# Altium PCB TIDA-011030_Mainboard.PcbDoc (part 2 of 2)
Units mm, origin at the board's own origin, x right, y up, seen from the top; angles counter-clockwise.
Board outline 65 x 19.54 mm, 4 copper layers (Top Layer, Inner Layer 1, Inner Layer 2, Bottom Layer), stack 1.586 mm thick; 113 components, 53 nets, 288 pads, 190 vias.
Unrouted connection lines stored in the file: 190.
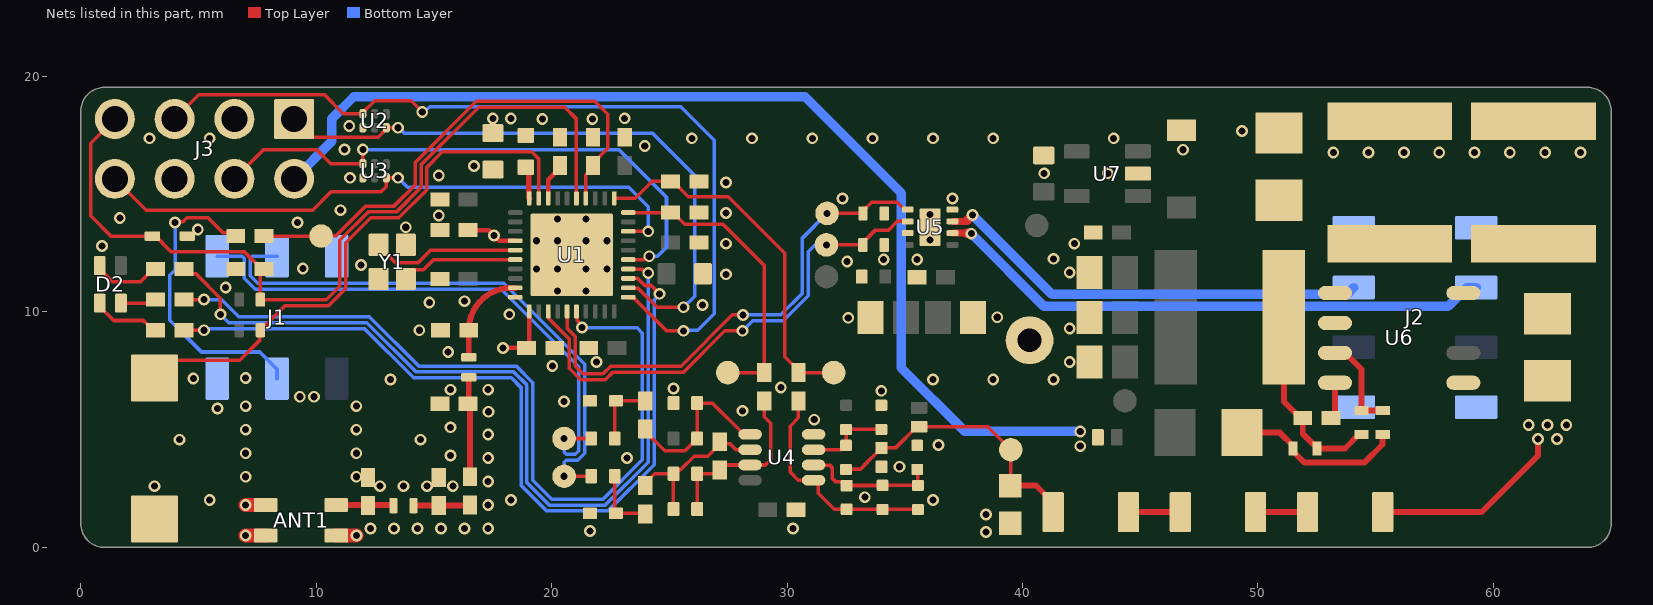
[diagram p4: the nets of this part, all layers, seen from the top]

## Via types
v1: diameter 0.5, hole 0.3, Top Layer to Bottom Layer, tented both sides, 186 vias
v2: diameter 0.443, hole 0.3, Top Layer to Bottom Layer, tented both sides, 4 vias

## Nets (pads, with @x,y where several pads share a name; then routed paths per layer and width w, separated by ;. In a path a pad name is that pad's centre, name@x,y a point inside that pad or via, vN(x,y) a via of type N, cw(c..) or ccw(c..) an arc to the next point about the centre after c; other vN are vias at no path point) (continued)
DRV_IN1/EN: R26.2 TP7.1 U1.3 U5.6 | length 21.3
  Top Layer w0.15: U1.3@19.85,10.025 19.875,10 19.875,9.725 20.747,8.853 20.747,7.603 21.225,7.125 22.281,7.125 22.604,7.448 25.604,7.448 27.356,9.2 v1(28.1,9.2) ; v1(31.67,12.85) R26.2@33.22,12.85 33.22,12.95 33.732,13.462 34.287,13.462 34.675,13.85 U5.6@35.12,13.85
  Bottom Layer w0.15: v1(28.1,9.2) 28.122,9.2 28.545,9.623 29.829,9.623 30.902,10.696 30.902,12.552 31.2,12.85 v1(31.67,12.85)
DRV_IN2/PWM: R25.2 TP8.1 U1.5 U5.5 | length 21.3
  Top Layer w0.15: U1.5@20.65,10.025 20.65,9.306 20.998,8.957 20.998,7.707 21.329,7.377 22.177,7.377 22.5,7.7 25.5,7.7 27.675,9.875 v1(28.125,9.875) ; v1(31.695,14.188) R25.2@33.223,14.188 33.223,14.288 33.6,14.665 34.68,14.665 34.995,14.35 U5.5@35.12,14.35
  Bottom Layer w0.15: v1(28.125,9.875) 29.725,9.875 30.65,10.8 30.65,13.143 v1(31.695,14.188)
DRV_OUT1: J2.4 U5.2 | length 23.9
  Top Layer w0.3: U5.2@37.02,13.35 v1@37.625,13.35
  Top Layer w0.4: v1@37.625,13.35 37.63,13.345 37.806,13.345 v1(37.825,13.326)
  Bottom Layer w0.4: v1(37.825,13.326) 40.913,10.238 58.068,10.238 58.87,11.04 J2.4@59.27,11.04
DRV_OUT2: J2.3 U5.3 | length 18.8
  Top Layer w0.3: U5.3@37.02,13.85 37.6,13.85 v1@37.7,13.95
  Top Layer w0.4: 37.65,13.9 v1(37.875,14.125)
  Bottom Layer w0.4: v1(37.875,14.125) 41.254,10.746 53.776,10.746 J2.3@54.07,11.04
GND: ANT1.2 ANT1.3 ANT1.4 C1.1 C2.2 C3.2 C5.2 C6.2 C7.2 C8.2 C9.2 C10.2 C11.2 C12.2 C13.2 C14.2 C16.1 C17.2 C18.2 C20.1 C21.2 C22.2 C23.2 C24.2 C25.2 C26.2 C29.2 C30.2 C31.2 C32.2 C33.2 C34.2 C35.2 D3.2 D7.2 D8.2 GND1.1 J1.1 J1.6 J2.1 J2.2 J3.3 J3.6 R9.1 R14.1 R17.1 R24.2 R25.1 R26.1 R27.1 SW1.1 U1.40 U1.41 U2.4 U3.4 U4.4 U5.4 U5.7 U5.9 U7.2 Y1.2 Y1.4 Z2.2 Z3.2 | length 2.6
  Top Layer w0.6: v1(7,0.5) ANT1.3@7.85,0.5 ; v1(7,1.8) ANT1.2@7.85,1.8 ; ANT1.4@10.85,0.5 11.7,0.5 ccw(c11.704,1.1) v1(11.702,0.5)
  other v1: 38.45,0.65 21.625,0.7 12.3,0.8 13.3,0.8 14.3,0.8 15.3,0.8 16.3,0.8 17.3,0.8 30.25,0.8 38.45,1.4 17.3,1.8 5.47,2.016 18.27,2.016 36.19,2.016 33.299,2.134 3.125,2.6 12.7,2.6 13.7,2.6 14.7,2.6 15.8,2.6 17.3,2.8 7,3 11.7,3 34.775,3.425 17.3,3.8 23.2,3.8 15.7,3.9 7,4 11.7,4 36.425,4.35 4.19,4.576 14.43,4.576 17.3,4.8 7,5 11.7,5 15.7,5.1 31.15,5.425 17.309,5.761 28.1,5.8 5.8,5.9 7,6 11.7,6 20.525,6.2 9.3,6.4 9.9,6.4 34,6.65 15.7,6.7 17.3,6.7 25.175,6.75 29.732,6.796 13.15,7.136 36.19,7.136 38.75,7.136 41.31,7.136 4.775,7.175 7,7.2 20.025,7.7 21.9,7.875 42,7.875 15.6,8.3 14.375,9.225 42,9.3 32.595,9.75 38.925,9.775 18.2,9.9 26.4,10.3 14.8,10.4 16.291,10.46 6.148,11.037 27.4,11.6 42,11.675 19.35,11.825 20.25,11.825 21.45,11.825 22.35,11.825 9.425,11.85 11.9,12 32.55,12.15 34.1,12.225 35.525,12.225 41.31,12.256 0.9,12.8 27.4,12.9 42.2,12.9 19.35,13.025 20.25,13.025 21.45,13.025 22.35,13.025 36.07,13.05 4.966,13.505 13.8,13.6 9.2,13.8 1.651,13.992 15.2,14.1 36.07,14.15 27.4,14.2 11.025,14.325 32.35,14.816 37.025,14.825 27.4,15.5 11.425,15.7 15.2,15.8 40.918,15.891 43.618,15.891 16.7,16.2 53.2,16.775 54.7,16.775 56.2,16.775 57.7,16.775 59.2,16.775 60.7,16.775 62.2,16.775 63.7,16.775 11.2,16.9 46.818,16.891 23.95,17.05 2.91,17.376 5.47,17.376 25.95,17.376 28.51,17.376 31.07,17.376 33.63,17.376 36.19,17.376 38.75,17.376 43.87,17.376 49.318,17.691 11.4,17.9 19.6,18.2 21.725,18.2 23.1,18.225
  other v2: 20.25,10.897 21.45,10.897 20.25,13.953 21.45,13.953
I_N: FB1.2 J1.4 TP4.1 | length 24.2
  Top Layer w0.15: v1(20.525,3.023) FB1.2@21.675,3.023
  Bottom Layer w0.15: J1.4@8.33,12.37 7.274,12.37 7.186,12.282 7.186,11.539 7.511,11.214 17.967,11.214 21.4,7.781 21.4,4 21.098,3.698 20.613,3.698 20.525,3.61 v1(20.525,3.023)
I_P: FB2.2 J1.2 TP6.1 | length 23.8
  Top Layer w0.15: v1(20.525,4.625) FB2.2@21.675,4.625
  Bottom Layer w0.15: J1.2@5.79,12.37 6.846,12.37 6.934,12.282 6.934,11.435 7.407,10.963 17.862,10.963 21.148,7.677 21.148,4.104 20.994,3.95 20.613,3.95 20.525,4.038 v1(20.525,4.625)
LED_B: R4.2 U1.14 | length 36.4
  Top Layer w0.15: R4.2@4.375,11.825 4.584,11.616 4.898,11.616 5.925,10.589 v1(5.925,9.9) ; U1.14@23.25,11.825 23.831,11.825 24.005,11.65 v1(24.1,11.65)
  Bottom Layer w0.15: v1(5.925,9.9) 6.277,9.548 12.146,9.548 14.243,7.452 18.393,7.452 18.948,6.896 18.948,2.746 19.896,1.798 22.279,1.798 24.1,3.619 v1(24.1,11.65)
LED_G: R3.2 U1.13 | length 35.6
  Top Layer w0.15: R3.2@4.375,9.225 v1(5.225,9.225) ; U1.13@23.25,11.425 23.654,11.425 23.954,11.125 24.222,11.125 24.479,10.868 24.479,10.676 v1(24.575,10.772)
  Bottom Layer w0.15: v1(5.225,9.225) 5.292,9.292 5.483,9.292 5.488,9.297 12.042,9.297 14.138,7.2 18.288,7.2 18.697,6.792 18.697,2.642 19.792,1.547 22.383,1.547 24.353,3.517 24.353,10.509 24.575,10.731 v1(24.575,10.772)
LED_R: R2.2 U1.6 | length 35
  Top Layer w0.15: R2.2@4.375,10.525 v1(5.225,10.525) ; U1.6@21.05,10.025 21.075,10 21.075,9.647 21.239,9.483 21.239,9.339 v1(21.288,9.339)
  Bottom Layer w0.15: v1(5.225,10.525) 5.978,10.525 6.703,9.8 12.25,9.8 14.347,7.703 18.497,7.703 19.2,7 19.2,2.85 20,2.05 22.175,2.05 23.848,3.723 23.848,9.102 23.625,9.325 21.302,9.325 v1(21.288,9.339)
Line: D6.2 J2.7 J2.8 R10.2 | length 8.3
  Top Layer w0.25: R10.2@55.3,1.5 59.5,1.5 61.9,3.9 v1(61.9,4.6)
  other v1: 62.7,4.6 61.5,5.2 62.3,5.2 63.1,5.2
MCU_ADC_I: C21.1 R21.2 TP5.1 U1.20 | length 12.8
  Top Layer w0.15: U1.20@23.25,14.225 25.046,14.225 C21.1@25.05,14.229 25.15,14.229 25.654,13.725 27.275,13.725 29.025,11.975 R21.2@29.025,7.425 TP5.1@27.475,7.425
MCU_ADC_V: C17.1 R13.2 TP3.1 U1.21 | length 15.6
  Top Layer w0.15: U1.21@22.65,14.825 23.55,14.825 24.275,15.55 C17.1@25.05,15.55 25.15,15.55 25.8,14.9 27.5,14.9 29.9,12.5 29.9,8.1 30.475,7.525 R13.2@30.475,7.425 TP3.1@31.975,7.425
MCU_RST: C13.1 D3.1 J3.7 R1.1 U1.25 | length 36.2
  Top Layer w0.15: J3.7@1.44,18.195 0.413,17.168 0.413,14.087 1.275,13.225 D3.1@3.035,13.225 3.17,13.225 3.845,12.55 6.95,12.55 7.675,11.825 C13.1@7.775,11.825 ; C13.1@7.725,11.775 7.625,11.675 R1.1@7.625,10.525 10.425,10.525 11,11.1 11,13.044 12.204,14.248 13.404,14.248 14.448,15.293 14.448,16.248 16.898,18.698 20.552,18.698 21.05,18.2 U1.25@21.05,14.825
MCU_SW: R5.1 SW1.2 U1.29 | length 24
  Top Layer w0.15: SW1.2@3.125,7.2 3.875,7.95 6.75,7.95 7.588,8.788 7.588,9.188 8.673,10.273 10.529,10.273 11.252,10.996 11.252,12.94 12.308,13.997 13.508,13.997 14.7,15.188 14.7,16.144 15.356,16.8 19.15,16.8 19.45,16.5 U1.29@19.45,14.825
MCU_SWDCK: J3.1 U1.12 U2.6 | length 26.8
  Top Layer w0.15: J3.1@9.06,18.195 9.83,17.425 12.625,17.425 U2.6@12.975,17.775 ; U2.6@12.975,17.825 v1(13.474,17.825) ; U1.12@23.25,11.025 23.275,11 23.675,11 24.475,10.2 v1(25.6,10.2)
  Bottom Layer w0.15: v1(13.474,17.825) 13.512,17.825 13.737,17.6 24.275,17.6 26.075,15.8 26.075,10.675 v1(25.6,10.2)
MCU_SWDIO: J3.5 U1.11 U2.3 | length 36.7
  Top Layer w0.15: J3.5@3.98,18.195 5.007,19.222 10.35,19.222 11.147,18.425 U2.3@11.975,18.425 11.975,18.475 12.475,18.975 14.025,18.975 v1(14.5,18.5) ; U1.11@23.25,10.625 23.275,10.6 23.475,10.6 24.875,9.2 v1(25.6,9.2)
  Bottom Layer w0.15: v1(14.5,18.5) 14.588,18.5 14.813,18.725 25.475,18.725 26.9,17.3 26.9,9.925 26.2,9.225 25.625,9.225 v1(25.6,9.2)
MCU_Temp: C14.1 R6.2 TP1.1 U1.24 | length 21.7
  Top Layer w0.15: R6.2@7.775,13.225 TP1.1@10.2,13.225 10.212,13.237 10.837,13.237 12.1,14.5 13.3,14.5 14.197,15.397 14.197,16.353 16.794,18.95 21.825,18.95 22.375,18.4 22.375,16.95 21.75,16.325 C14.1@21.75,16.225 21.75,16.125 21.45,15.825 U1.24@21.45,14.825
NetANT1_1: ANT1.1 Z1.1 Z2.1 | length 2.4
  Top Layer w0.248: ANT1.1@10.85,1.8 13.25,1.8 cw(c13.25,1.775) Z1.1@13.275,1.775
NetC1_2: C1.2 U1.28 | length 1.6
  Top Layer w0.2: U1.28@19.85,14.825 19.85,15.625 20.35,16.125 C1.2@20.35,16.225
NetC4_1: C4.1 C5.1 L1.1 | length 4.3
  Top Layer w0.248: C5.1@16.45,6.1 cw(c16.45,6.025) 16.525,6.025 C4.1@16.525,3 ; C5.1@16.475,6.075 L1.1@16.475,7.225
NetC4_2: C4.2 Z1.2 Z3.1 | length 2.4
  Top Layer w0.248: Z1.2@14.125,1.775 16.349,1.775 C4.2@16.525,1.8
NetC6_1: C6.1 L1.2 U1.39 | length 4.2
  Top Layer w0.248: L1.2@16.475,8.075 C6.1@16.475,9.225 cw(c18.275,9.225) 18.275,11.025 U1.39@18.45,11.025
NetC15_1: C15.1 R7.1 R8.1 R9.2 U4.2 | length 5.8
  Top Layer w0.15: U4.2@31.125,3.5 31.127,3.498 31.802,3.498 31.925,3.375 31.925,2.925 32.054,2.796 32.352,2.796 C15.1@32.527,2.621 32.535,2.629 34.045,2.629 R7.1@34.053,2.637 34.055,2.636 35.553,2.636 35.54,2.649 35.54,3.296 R9.2@35.525,3.311
NetC15_2: C15.2 R7.2 R8.2 R13.1 U4.1 | length 9.5
  Top Layer w0.15: R13.1@30.475,6.225 30.475,5.5 30.125,5.15 30.125,3.2 30.475,2.85 U4.1@31.125,2.85 31.186,2.85 31.325,2.711 31.325,2.3 32.004,1.621 C15.2@32.527,1.621 32.531,1.617 34.049,1.617 R7.2@34.053,1.612 34.055,1.611 35.553,1.611 R8.2@35.555,1.609
NetC16_2: C16.2 D4.2 R12.1 R14.2 R15.1 TP2.1 | length 12.2
  Top Layer w0.15: R15.1@32.502,3.311 33.099,3.311 33.394,3.605 33.394,3.617 33.867,4.09 33.878,4.09 C16.2@34.013,4.225 34.605,4.225 35.505,5.125 D4.2@35.605,5.125 38.525,5.125 TP2.1@39.5,4.15 R14.2@39.5,2.65
  Top Layer w0.25: R14.2@39.5,2.65 R14.2@39.475,2.625 40.575,2.625 41.3,1.9 R12.1@41.3,1.5
NetC19_1: C19.1 R18.1 R19.1 R21.1 U4.7 | length 7.5
  Top Layer w0.15: R18.1@26.187,1.625 26.187,3.127 26.975,3.127 C19.1@27.138,3.29 27.348,3.5 U4.7@28.425,3.5 29.075,3.5 29.3,3.725 29.3,5.275 29.025,5.55 R21.1@29.025,6.225
NetC19_2: C19.2 R18.2 R19.2 R20.2 U4.6 | length 7
  Top Layer w0.15: R20.2@23.975,2.625 23.975,2.725 24.377,3.127 R19.2@25.162,3.127 ; R18.2@25.162,1.625 R19.2@25.162,3.127 ; U4.6@28.425,4.15 28.419,4.156 27.819,4.156 27.575,4.4 27.229,4.4 27.188,4.44 C19.2@27.138,4.49 27.138,4.39 26.624,3.876 26.048,3.876 25.469,3.296 25.325,3.296 25.162,3.134 R19.2@25.162,3.127
NetC20_2: C20.2 FB1.1 R20.1 | length 2.9
  Top Layer w0.15: FB1.1@22.675,3.023 22.675,1.496 C20.2@22.725,1.446 23.954,1.446 R20.1@23.975,1.425
NetC22_1: C22.1 FB2.1 R23.1 | length 2.9
  Top Layer w0.15: FB2.1@22.675,4.625 22.675,6.175 C22.1@22.725,6.225 R23.1@23.975,6.225
NetC27_1: C27.1 D5.1 R28.2 | length 7.4
  Top Layer w0.25: D5.1@49.325,4.875 50.931,4.875 51.492,4.314 C27.1@51.492,4.2 51.492,4.086 51.978,3.6 54.519,3.6 55.292,4.373 55.292,4.784 R28.2@55.3,4.792
NetC27_2: C27.2 C28.2 D8.1 L3.1 R29.1 U6.1 U6.2 | length 8.4
  Top Layer w0.25: L3.1@51.1,9.775 51.1,6.2 51.8,5.5 C28.2@51.9,5.5 51.9,4.825 52.345,4.38 52.443,4.38 52.508,4.314 C27.2@52.508,4.2 53.694,4.2 54.286,4.792 R29.1@54.4,4.792
NetC28_1: C28.1 U6.4 | length 1.6
  Top Layer w0.25: C28.1@53.1,5.5 53.275,5.675 U6.4@53.275,6.995
NetC29_1: C29.1 C30.1 D6.1 U6.5 U6.8
NetD1_2: D1.2 J3.2 | length 45.6
  Bottom Layer w0.4: J3.2@9.06,15.655 10.65,17.245 10.65,18.2 11.59,19.14 30.76,19.14 34.85,15.05 34.85,7.625 37.55,4.925 v1(42.45,4.925)
  other v1: 42.45,4.3
NetD2_1: D2.1 R2.1 | length 1.5
  Top Layer w0.15: D2.1@1.7,10.375 3.025,10.375 R2.1@3.175,10.525
NetD2_2: D2.2 R3.1 | length 2.9
  Top Layer w0.15: D2.2@0.8,10.375 0.8,10.225 1.387,9.637 2.645,9.637 2.833,9.45 2.95,9.45 R3.1@3.175,9.225
NetD2_3: D2.3 R4.1 | length 3
  Top Layer w0.15: D2.3@0.8,11.975 0.8,11.825 1.35,11.275 2.525,11.275 3.075,11.825 R4.1@3.175,11.825
NetJ1_3: J1.3 R6.1 | length 13
  Top Layer w0.15: v1(4,13.8) 4.036,13.836 4.336,13.836 4.5,14 5.4,14 6.038,13.362 6.438,13.362 R6.1@6.575,13.225
  Bottom Layer w0.15: v1(4,13.8) 4,11.79 3.775,11.565 3.775,9.65 5.125,8.3 7.6,8.3 7.905,7.995 8.33,7.57 J1.3@8.33,7.17
NetL2_1: L2.1 U1.30 | length 1.4
  Top Layer w0.25: L2.1@18.9,16.15 19.025,16.025 19.025,14.85 U1.30@19.05,14.825
NetR10_1: R10.1 R11.2 | length 2.2
  Top Layer w0.25: R11.2@49.9,1.5 R10.1@52.1,1.5
NetR11_1: R11.1 R12.2 | length 2.2
  Top Layer w0.25: R12.2@44.5,1.5 R11.1@46.7,1.5
NetR15_2: R15.2 R16.1 R17.2 U4.3 | length 3.6
  Top Layer w0.15: U4.3@31.125,4.15 32.303,4.15 32.489,4.336 R15.2@32.502,4.336 R16.1@32.502,5.013 R17.2@34.003,5.012
NetR22_2: R22.2 R23.2 R24.1 U4.5 | length 7.2
  Top Layer w0.15: R23.2@23.975,5.025 23.975,4.925 24.8,4.1 25.659,4.1 26.012,4.454 26.025,4.454 26.187,4.616 26.187,4.629 26.187,6.131 26.819,6.131 28.15,4.8 U4.5@28.425,4.8
NetR28_1: R28.1 R29.2 U6.3 | length 4.1
  Top Layer w0.25: U6.3@53.275,8.265 53.7,8.265 54.4,7.565 R29.2@54.4,5.808 R28.1@55.3,5.808
NetU1_35: U1.35 Y1.3 | length 6.4
  Top Layer w0.15: Y1.3@12.65,12.85 12.65,12.8 13.35,12.1 14.325,12.1 14.85,12.625 U1.35@18.45,12.625
NetU1_36: U1.36 Y1.1 | length 5
  Top Layer w0.15: Y1.1@13.8,11.4 13.8,11.45 14.15,11.8 14.55,11.8 14.975,12.225 U1.36@18.45,12.225
UART_RX: J3.8 U1.18 U3.6 | length 26.4
  Top Layer w0.15: J3.8@1.44,15.655 2.77,14.325 9.85,14.325 10.625,15.1 12.75,15.1 12.975,15.325 U3.6@12.975,15.7 v1(13.475,15.7) ; U1.18@23.25,13.425 v1(24.1,13.425)
  Bottom Layer w0.15: v1(13.475,15.7) 13.875,15.3 23.275,15.3 24.1,14.475 v1(24.1,13.425)
UART_TX: J3.4 U1.15 U3.3 | length 24.5
  Top Layer w0.15: J3.4@6.52,15.655 7.765,16.9 10.007,16.9 10.607,16.3 U3.3@11.975,16.3 v1(11.975,16.9) ; U1.15@23.25,12.225 23.905,12.225 24.047,12.367 v1(24.142,12.367)
  Bottom Layer w0.15: v1(11.975,16.9) 22.85,16.9 24.875,14.875 24.875,12.75 24.492,12.367 v1(24.142,12.367)
VDDR: C2.1 C3.1 C12.1 L2.2 U1.1 U1.34 | length 4.8
  Top Layer w0.2: C3.1@16.45,13.475 17.325,13.475 v1(17.55,13.25) 17.775,13.025 U1.34@18.45,13.025 ; v1(17.925,8.475) C2.1@18.925,8.475 19.05,8.6 U1.1@19.05,10.025
  other v1: 17.499,18.223 18.263,18.22
pads on no net: J2.5 J2.6 U1.2 U1.4 U1.7 U1.9 U1.10 U1.16 U1.19 U1.22 U1.26 U1.27 U1.32 U1.33 U1.37 U2.2 U2.5 U3.2 U3.5 U6.6 U7.3 U7.4

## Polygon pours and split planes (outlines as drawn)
GND on Top Layer "Top Layer-GND" (solid, remove dead copper, pour order 36): 43.8,15.489 43.5,15.205 43.5,0 11.35,0 11.35,6 7.35,6 7.35,0 0,0 0,19.5 65,19.5 65,16.4 47.7,16.4 47.4,16.1 47.4,15.7 47.189,15.489
5V on Top Layer "TOP_LAYER_5V_P000" (solid, remove dead copper, pour order 0): 37.5,13 36.75,13 36.75,12.625 36.325,12.2 36.325,11.2 35.6,10.475 34.5,10.475 34.5,9.075 36.95,9.075 36.95,10.475 37.5,11.025
VDDR on Top Layer "TOP_LAYER_VDDR_P001" (solid, remove dead copper, pour order 1): 19.25,17 15.3,17 15.3,18.575 19.25,18.575
NetD1_2 on Top Layer "TOP_LAYER_NETD1_2_P030" (solid, remove dead copper, pour order 30): 42.15,5.25 42.15,4 43.45,4 43.45,5.25
5V on Top Layer "Top Layer-5V" (solid, remove dead copper, pour order 28): 43.7,4.375 44.2,3.875 47.4,3.875 47.4,15.175 47.2,15.375 43.9,15.375 43.7,15.175 43.7,6.275 43.7,5.175
NetC29_1 on Top Layer "TOP_LAYER_NETC29_1_P005" (solid, remove dead copper, pour order 5): 60,6.6 59.6,6.2 57.6,6.2 57.2,6.6 57.2,9.6 54.7,12.1 52.95,12.1 52.95,13.7 64.9,13.7 64.9,9 60.4,9 60,8.6
NetC27_2 on Top Layer "TOP_LAYER_NETC27_2_P010" (solid, remove dead copper, pour order 10): 54.1,11.275 54.1,9.175 52.4,9.175 52.2,8.975 52.2,6.875 50.2,6.875 50.2,12.6 49.8,13 49.8,15.675 51.925,15.675 52,15.6 52,11.775 52.5,11.275
Line on Top Layer "TOP_LAYER_LINE_P023" (solid, remove dead copper, pour order 23): 61.2,8 63.4,8 63.4,4.3 61.2,4.3
3.3V on Top Layer "TOP_LAYER_3.3V_P024" (solid, remove dead copper, pour order 24): 43,15.575 40.3,15.575 40.3,13.375 43,13.375
Line on Bottom Layer "BOTTOM_LAYER_LINE_P037" (solid, remove dead copper, pour order 37): 53.1,6.5 53.1,4.1 63.9,4.1 63.9,6.5
GND on Bottom Layer "Bottom Layer-GND" (solid, remove dead copper, pour order 34): 0,0 7.35,0 7.35,6 11.35,6 11.35,0 50.8,0 50.8,9.1 65,9.1 65,19.5 0,19.5
NetD1_2 on Bottom Layer "BOTTOM_LAYER_NETD1_2_P025" (solid, remove dead copper, pour order 25): 42.15,5.25 42.15,4 42.75,4 42.75,5.25
GND on Inner Layer 1 "Inner Layer 1-GND" (solid, remove dead copper, pour order 33): 0,0 7.35,0 7.35,6 11.35,6 11.35,0 65,0 65,2.6 59.5,2.6 59.5,7.2 63.1,7.2 65,7.2 65,19.5 0,19.5
VDDR on Inner Layer 2 "INNER_LAYER_2_VDDR_P029" (solid, remove dead copper, pour order 29): 17.2,18.4 17.2,16 17.2,14.4 17.2,8.4 17.4,8.2 18.3,8.2 18.5,8.4 18.5,18.4 18.4,18.5 17.3,18.5
3.3V on Inner Layer 2 "Inner Layer 2-3.3V" (solid, remove dead copper, pour order 32): 0,0 7.35,0 7.35,6 11.35,6 11.35,0 45.4,0 45.4,19.5 0,19.5

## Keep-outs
Keep-Out Layer:
  text ".Layer_Name" at 14.656,-21.806 h1.52

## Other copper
Top Layer:
  text ".Layer_Name" at 14.656,-21.806 h1.52
Bottom Layer:
  text ".Layer_Name" at 14.656,-21.806 h1.52

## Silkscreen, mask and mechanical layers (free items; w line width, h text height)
Top Overlay:
  circle w0.254: c31.468,2.121 r0.141
  circle w0.254: c11,18.2 r0.141
  lines w0.2: 12.95,16.8 13.45,16.8 13.45,16.4 ; 12.95,18.9 13.45,18.9 13.45,18.5
  text "TLV709A33" at 38.45,17.825 h0.76
  text ".PRJ_Number" at 25.41,17.052 h1.1
  text "DRV8213" at 32.142,15.05 h0.76
  text "CC234x" at 22.847,9 h0.76
  text "UCC28881" at 53.7,3.2 h0.76
  text "OPA2323" at 31.2,0.225 h0.76
  text ".Layer_Name" at 14.656,-21.806 h1.52
Bottom Overlay:
  lines w0.2: 12,16.9 26.7,16.9 ; 15,15.5 15,18.3 ; 19.3,15.5 19.3,18.3 ; 22.2,15.5 22.2,18.3 ; 12,15.5 12,18.3 26.7,18.3 26.7,15.5 12,15.5
  text "RST" at 14.516,17.219 h0.76
  text "SWDIO" at 18.914,17.219 h0.76
  text "GND" at 21.816,17.219 h0.76
  text "SWDCK" at 26.177,17.219 h0.76
  text "RX" at 14.235,15.819 h0.76
  text "GND" at 18.216,15.819 h0.76
  text "TX" at 21.435,15.819 h0.76
  text "5V" at 25.035,15.819 h0.76
  text "DANGER HIGH VOLTAGE" at 64,1.1 h1.52
  text ".Layer_Name" at 14.656,-21.806 h1.52
Top Paste:
  text ".Layer_Name" at 14.656,-21.806 h1.52
Bottom Paste:
  text ".Layer_Name" at 14.656,-21.806 h1.52
Top Solder:
  text ".Layer_Name" at 14.656,-21.806 h1.52
  text ".Layer_Name" at 14.656,-21.806 h1.52
Bottom Solder:
  text ".Layer_Name" at 14.656,-21.806 h1.52
Drill Guide:
  text ".Layer_Name" at 14.656,-21.806 h1.52
M1 Board Outline:
  the board outline again, w0.254
  text ".Layer_Name" at 14.656,-21.806 h1.52
M2 Board Dimensions:
  rectangle: 3.175,-10.16 12.7,-6.985
  rectangle: 0,-6.985 3.175,-3.81
  lines w0.178: 0,-6.985 25.4,-6.985 ; 3.175,-10.16 3.175,-3.81 ; 6.35,-10.16 6.35,-3.81 ; 12.7,-10.16 12.7,-3.81 ; 19.05,-10.16 19.05,-3.81 ; 0,-10.16 0,-3.81 25.4,-3.81 25.4,-10.16 0,-10.16
  text ".Layer_Name" at 14.656,-21.806 h1.52
M3 3D STEP Top:
  text ".Layer_Name" at 14.656,-21.806 h1.52
M4 3D STEP Bottom:
  text ".Layer_Name" at 14.656,-21.806 h1.52
M5 Assembly Top:
  lines w0.254: -7.417,-23.626 160.223,-23.626 ; -7.417,-18.462 160.274,-18.462 ; -7.417,-13.297 -7.417,-28.791 94.31,-28.791 160.274,-28.791 160.274,-13.297 -7.404,-13.297 -7.404,-28.791 32.614,-28.791 ; 55.194,-28.791 55.194,-13.297 ; 87.376,-18.462 87.376,-13.297 ; 108.712,-18.462 108.712,-13.297 ; 124.511,-28.956 124.511,-23.804
  text "COMPONENTS MARKED 'DNP' SHOULD NOT BE POPULATED." at 29.299,-8.09 h1.52
  text "ASSEMBLY VARIANT:" at 29.286,-11.024 h1.52
  text ".VariantName" at 55.601,-11.024 h1.52
  text "PCB VIEWED FROM TOP SIDE" at -5.804,-16.654 h1.52
  text "BOARD #:" at 57.099,-16.654 h1.52
  text ".PRJ_Number" at 70.955,-16.654 h1.52
  text "REV:" at 92.405,-16.654 h1.52
  text ".PCB_Rev" at 99.809,-16.654 h1.52
  text "SVN REV:" at 113.69,-16.654 h1.52
  text ".VersionControl_RevNumber" at 126.543,-16.654 h1.52
  text "PLOT NAME =" at -5.804,-27.034 h1.52
  text ".plot_File_Name" at 14.656,-27.034 h1.52
  text "GENERATED    :" at 57.15,-27.034 h1.52
  text ".Print_Date" at 79.235,-27.034 h1.52
  text ".Print_Time" at 97.752,-27.034 h1.52
  text "TEXAS INSTRUMENTS" at 129.87,-27.034 h1.52
M6 Assembly Bottom:
  lines w0.254: -7.429,-18.474 160.261,-18.474 ; -7.379,-23.639 160.261,-23.639 ; 28.334,-28.969 28.334,-23.817 ; 44.133,-18.474 44.133,-13.31 ; 65.468,-18.474 65.468,-13.31 ; 97.65,-28.804 97.65,-13.31 ; 120.231,-28.804 160.249,-28.804 160.249,-13.31 -7.429,-13.31 -7.429,-28.804 58.534,-28.804 160.261,-28.804 160.261,-13.31
  text "COMPONENTS MARKED 'DNP' SHOULD NOT BE POPULATED." at 154.991,-8.077 h1.52
  text ".VariantName" at 128.473,-11.024 h1.52
  text "ASSEMBLY VARIANT:" at 154.864,-11.024 h1.52
  text ".VersionControl_RevNumber" at 26.302,-16.667 h1.52
  text "SVN REV:" at 39.154,-16.667 h1.52
  text ".PCB_Rev" at 53.035,-16.667 h1.52
  text "REV:" at 60.439,-16.667 h1.52
  text ".PRJ_Number" at 81.89,-16.667 h1.52
  text "BOARD #:" at 95.745,-16.667 h1.52
  text "PCB VIEWED FROM BOTTOM SIDE" at 158.648,-16.667 h1.52
  text "TEXAS INSTRUMENTS" at 22.974,-27.047 h1.52
  text ".Print_Time" at 55.093,-27.047 h1.52
  text ".Print_Date" at 73.609,-27.047 h1.52
  text "GENERATED    :" at 95.694,-27.047 h1.52
  text ".plot_File_Name" at 138.189,-27.047 h1.52
  text "PLOT NAME =" at 158.648,-27.047 h1.52
M9 Title Sheet:
  drawing of 63 lines, arcs and shapes, not listed
  text "1" at 35.293,466.75 h1.78
  text "2" at 136.766,466.75 h1.78
  text "3" at 238.239,466.75 h1.78
  text "4" at 339.865,466.75 h1.78
  text "5" at 441.423,466.75 h1.78
  text "6" at 542.98,466.75 h1.78
  text "7" at 644.623,466.75 h1.78
  text "8" at 746.096,466.75 h1.78
  text "A" at -11.874,405.841 h1.78
  text "A" at 793.305,405.841 h1.78
  text "B" at -11.874,278.841 h1.78
  text "B" at 793.305,278.841 h1.78
  text "C" at -11.874,151.841 h1.78
  text "C" at 793.305,151.841 h1.78
  text "D" at -11.874,24.841 h1.78
  text "D" at 793.305,24.841 h1.78
  text "PROJECT TITLE:" at 714.947,6.823 h1.14
  text ".PRJ_Title" at 716.216,3.436 h1.78
  text "DESIGNED FOR:" at 714.947,-0.823 h1.14
  text ".PRJ_Customer" at 716.216,-4.379 h1.78
  text "FILE NAME:" at 714.947,-8.443 h1.14
  text ".PCB_File_Name_No_Path" at 716.216,-11.491 h1.78
  text "Texas Instruments (TI) and/or its licensors do not warrant the accuracy or completeness of this specification" at 588.721,-15.601 h1.14
  text "ENGINEER:" at 714.947,-15.809 h1.14
  text "LAYOUT BY:" at 753.173,-15.809 h1.14
  text "or any information contained therein. TI and/or its licensors do not warrant that this design will meet" at 587.579,-18.463 h1.14
  text ".PRJ_Engineer" at 716.216,-19.746 h1.78
  text ".PCB_Layout" at 754.456,-19.746 h1.78
  text "the specifications, will be suitable for your application or fit for any particular purpose, or will operate in" at 587.579,-21.325 h1.14
  text ".Layer_Name" at 14.656,-21.806 h1.52
  text "ALTIUM DESIGNER VERSION:" at 753.173,-23.683 h1.14
  text "an implementation. TI and/or its licensors do not warrant that the design is production worthy. You should" at 587.579,-24.187 h1.14
  text "completely validate and test your design implementation to confirm the system functionality for your application." at 588.721,-27.048 h1.14
  text ".print_Scale" at 716.216,-27.069 h1.78
  text ".Application_BuildNumber" at 754.456,-27.069 h1.78
  text "1" at 35.293,-33.503 h1.78
  text "2" at 136.766,-33.503 h1.78
  text "3" at 238.239,-33.503 h1.78
  text "4" at 339.865,-33.503 h1.78
  text "5" at 441.423,-33.503 h1.78
  text "6" at 542.98,-33.503 h1.78
  text "7" at 644.623,-33.503 h1.78
  text "8" at 746.096,-33.503 h1.78
M10 Fab Notes:
  drawing of 189 lines, arcs and shapes, not listed
  text "DESIGN INFORMATION" at 741.376,161.675 h1.52
  text "MIN. TRACK WIDTH:" at 725.004,158.319 h1.52
  text "8" at 752.848,158.32 h1.52
  text "MIL" at 756.779,158.319 h1.52
  text "MIN. CLEARANCE:" at 725.004,155.167 h1.52
  text "7.874" at 748.5,155.167 h1.52
  text "MIL" at 756.779,155.167 h1.52
  text "MIN. VIA PAD SIZE:" at 725.004,152.014 h1.52
  text "24" at 752.087,152.014 h1.52
  text "MIL" at 756.779,152.014 h1.52
  text "0.05mm (2MIL)" at 742.657,148.714 h1.52
  text "MINIMUM ANNULAR RING" at 716.641,148.506 h1.52
  text "EXTERNAL" at 760.64,148.506 h1.52
  text "PER" at 721.721,145.708 h1.52
  text "IPC-D-275 CLASS 2 LEVEL C" at 727.309,145.708 h1.52
  text "MIL, HOLES" at 765.11,143.156 h1.52
  text "+/-" at 755.142,142.938 h1.52
  text "+/-" at 776.834,142.938 h1.52
  text "REGISTRATION TOLERANCES:" at 716.641,142.911 h1.52
  text "METAL" at 747.116,142.911 h1.52
  text "5" at 761.751,142.911 h1.52
  text "3" at 782.909,142.911 h1.52
  text "MIL" at 785.862,142.911 h1.52
  text "HOLE SIZE TOLERANCE (UNLESS OTHERWISE SPECIFIED):" at 716.641,140.414 h1.52
  text "+/-" at 776.834,140.341 h1.52
  text "3" at 782.909,140.314 h1.52
  text "MIL" at 785.862,140.314 h1.52
  text "MATERIAL:" at 714.742,136.818 h1.52
  text "FR-4 High Tg" at 739.798,133.553 h1.52
  text "X" at 736.129,133.35 h1.52
  text "FR-4" at 725.436,133.235 h1.52
  text "OTHER" at 763.231,133.235 h1.52
  text "62 MIL (1.6mm) +/-10%" at 733.566,129.602 h1.52
  text "X" at 730.516,129.54 h1.52
  text "THICKNESS:" at 716.641,129.394 h1.52
  text "OTHER" at 766.203,129.394 h1.52
  text "TOLERANCE:" at 716.641,125.88 h1.52
  text "X" at 738.187,125.88 h1.52
  text "ANSI IPC-6012 TYPE 3 CLASS 2" at 742.708,125.88 h1.52
  text "OTHER +/-" at 742.708,122.218 h1.52
  text "BOW & TWIST:" at 716.641,118.53 h1.52
  text "X" at 738.187,118.53 h1.52
  text "ANSI IPC-6012 TYPE 3 CLASS 2" at 742.708,118.53 h1.52
  text "OTHER +/-" at 742.708,114.804 h1.52
  text "DRILLING:" at 714.742,111.486 h1.52
  text "NC_DRILL FILES" at 759.472,108.815 h1.52
  text "REFERENCE:" at 716.641,108.715 h1.52
  text "X" at 733.335,108.712 h1.52
  text "AS SHOWN" at 737.856,108.715 h1.52
  text "X" at 756.221,108.715 h1.52
  text "OTHER" at 767.041,105.101 h1.52
  text "PTH COPPER THICKNESS:" at 716.633,105.012 h1.52
  text "X" at 745.57,105.012 h1.52
  text "20-30 um" at 748.821,105.012 h1.52
  text "BOARD FINISH:" at 714.742,101.263 h1.52
  text "SILKSCREEN:" at 718.685,98.466 h1.52
  text "X" at 743.013,98.466 h1.52
  text "TOP" at 745.984,98.466 h1.52
  text "X" at 755.967,98.466 h1.52
  text "BOTTOM" at 758.964,98.466 h1.52
  text "SILKSCREEN COLOR:" at 718.685,94.524 h1.52
  text "X" at 742.987,94.524 h1.52
  text "WHITE" at 745.984,94.524 h1.52
  text "OTHER" at 758.964,94.524 h1.52
  text "X" at 746.315,90.88 h1.52
  text "GREEN" at 749.312,90.88 h1.52
  text "OTHER" at 765.009,90.88 h1.52
  text "SOLDER RESIST COLOR:" at 718.685,90.706 h1.52
  text "X" at 746.315,86.962 h1.52
  text "MATTE" at 749.312,86.962 h1.52
  text "SEMI-GLOSS" at 764.997,86.946 h1.52
  text "IMMERSION GOLD (ENIG)" at 741.692,82.574 h1.52
  text "ENEPIG" at 775.665,82.39 h1.52
  text "SURFACE FINISH:" at 714.742,82.365 h1.52
  text "X" at 737.171,82.365 h1.52
  text "IMM. TIN/SILVER OR EQUIV" at 723.113,78.877 h1.52
  text "OTHER" at 759.472,78.777 h1.52
  text "ARRAY/PANEL:" at 714.742,74.831 h1.52
  text "CUT AND TRIM PER M1 BOARD OUTLINE" at 741.692,74.622 h1.52
  text "N.C. ROUTE" at 741.692,71.168 h1.52
  text "X" at 759.167,71.168 h1.52
  text "V. SCORE" at 763.688,71.168 h1.52
  text "CERTIFICATION:" at 714.742,67.888 h1.52
  text "MATERIALS AND WORKMANSHIP FOR ALL PCBS" at 733.157,67.888 h1.52
  text "TO MEET OR EXCEED THE REQUIREMENTS OF:" at 733.157,65.499 h1.52
  text "X" at 723.95,62.232 h1.52
  text "ANSI IPC-A-600F CLASS ->" at 727.201,62.232 h1.52
  text "X" at 769.06,62.232 h1.52
  text "2" at 771.854,62.232 h1.52
  text "1" at 763.853,62.194 h1.52
  text "3" at 780.846,62.194 h1.52
  text "X" at 744.575,58.481 h1.52
  text "RoHS" at 747.826,58.481 h1.52
  text "OTHER" at 764.194,58.481 h1.52
  text "PER ORDER" at 774.279,58.481 h1.52
  text "ALL BOARDS MUST MEET OR EXCEED UL94-V0 REQUIREMENTS." at 715.442,54.574 h1.52
  text "PCB MUST BEAR THE UL94V-0 UL REGISTERED MATERIAL ID NUMBER" at 715.442,51.626 h1.52
  text "ADDITIONAL REQUIREMENTS:" at 714.742,47.322 h1.52
  text "MICROSECTION:" at 716.641,44.601 h1.52
  text "YES" at 739.647,44.601 h1.52
  text "REQUIRED" at 761.529,40.935 h1.52
  text "BARE BOARD ELEC. TEST:" at 716.641,40.863 h1.52
  text "NONE" at 749.807,40.863 h1.52
  text "X" at 758.532,40.863 h1.52
  text "PER ORDER" at 776.566,40.863 h1.52
  text "XX MIL VIAS REQUIRE NON-CONDUCTIVE FILL AND PLANARIZE" at 720.912,35.657 h1.5
  text "XX MIL VIAS REQUIRE CONDUCTIVE FILL AND PLANARIZE" at 721.116,33.016 h1.52
  text "OUTER XX MIL TRACES REQUIRE 50 OHM SINGLE-ENDED IMPEDANCE" at 721.091,28.866 h1.47
  text "LAYER 2 & 3 (INNER LAYERS) XX MIL WIDE, XX MIL SPACE / TRACES REQUIRE 100 OHM DIFFERENTIAL IMPEDANCE" at 720.887,22.879 h1.52
  text ".Layer_Name" at 14.656,-21.806 h1.52
M11 Gerber Information:
  lines w0.254: -7.417,-23.626 160.223,-23.626 ; -7.417,-18.462 160.274,-18.462 ; -7.417,-13.297 -7.417,-28.791 94.31,-28.791 160.274,-28.791 160.274,-13.297 -7.404,-13.297 -7.404,-28.791 32.614,-28.791 ; 55.194,-28.791 55.194,-13.297 ; 87.376,-18.462 87.376,-13.297 ; 108.712,-18.462 108.712,-13.297 ; 124.511,-28.956 124.511,-23.804
  text "ALL ARTWORK VIEWED FROM TOP SIDE" at -5.804,-16.654 h1.52
  text "BOARD #:" at 57.099,-16.654 h1.52
  text ".PRJ_Number" at 70.955,-16.654 h1.52
  text "REV:" at 92.405,-16.654 h1.52
  text ".PCB_Rev" at 99.809,-16.654 h1.52
  text "SVN REV:" at 113.69,-16.654 h1.52
  text ".VersionControl_RevNumber" at 126.543,-16.654 h1.52
  text "LAYER NAME =" at -5.804,-21.806 h1.52
  text "PLOT NAME =" at -5.804,-27.034 h1.52
  text ".plot_File_Name" at 14.656,-27.034 h1.52
  text "GENERATED    :" at 57.15,-27.034 h1.52
  text ".Print_Date" at 79.235,-27.034 h1.52
  text ".Print_Time" at 97.752,-27.034 h1.52
  text "TEXAS INSTRUMENTS" at 129.87,-27.034 h1.52
M12 Stackup:
  drawing of 295 lines, arcs and shapes, not listed
  text "Layer" at 674.469,457.523 h1.52
  text "Name" at 684.88,457.523 h1.52
  text "Material" at 708.496,457.523 h1.52
  text "Thickness" at 730.334,457.523 h1.52
  text "Constant" at 746.84,457.523 h1.52
  text "Board Layer Stack" at 761.314,457.523 h1.52
  text "Top Overlay" at 684.88,454.475 h1.52
  text "Top Solder" at 684.88,451.427 h1.52
  text "Solder Resist" at 708.496,451.427 h1.52
  text "0.60mil" at 730.334,451.427 h1.52
  text "3.8" at 746.84,451.427 h1.52
  text "1" at 674.469,448.379 h1.52
  text "Top Layer" at 684.88,448.379 h1.52
  text "CF-004" at 708.496,448.379 h1.52
  text "1.38mil" at 730.334,448.379 h1.52
  text "Dielectric 1" at 684.88,445.331 h1.52
  text "NP-155F" at 708.496,445.331 h1.52
  text "8.28mil" at 730.334,445.331 h1.52
  text "4.4" at 746.84,445.331 h1.52
  text "2" at 674.469,442.283 h1.52
  text "Inner Layer 1" at 684.88,442.283 h1.52
  text "CF-004" at 708.496,442.283 h1.52
  text "0.60mil" at 730.334,442.283 h1.52
  text "Dielectric 2" at 684.88,439.235 h1.52
  text "NP-155F" at 708.496,439.235 h1.52
  text "41.93mil" at 730.334,439.235 h1.52
  text "4.43" at 746.84,439.235 h1.52
  text "3" at 674.469,436.187 h1.52
  text "Inner Layer 2" at 684.88,436.187 h1.52
  text "CF-004" at 708.496,436.187 h1.52
  text "0.60mil" at 730.334,436.187 h1.52
  text "Dielectric 3" at 684.88,433.139 h1.52
  text "NP-155F" at 708.496,433.139 h1.52
  text "8.28mil" at 730.334,433.139 h1.52
  text "4.4" at 746.84,433.139 h1.52
  text "4" at 674.469,430.091 h1.52
  text "Bottom Layer" at 684.88,430.091 h1.52
  text "CF-004" at 708.496,430.091 h1.52
  text "1.38mil" at 730.334,430.091 h1.52
  text "Bottom Solder" at 684.88,427.043 h1.52
  text "Solder Resist" at 708.496,427.043 h1.52
  text "0.60mil" at 730.334,427.043 h1.52
  text "3.8" at 746.84,427.043 h1.52
  text "Bottom Overlay" at 684.88,423.995 h1.52
  text ".Layer_Name" at 14.656,-21.806 h1.52
M13 Component Bodies Top:
  text ".Layer_Name" at 14.656,-21.806 h1.52
M14 Component Bodies Bottom:
  text ".Layer_Name" at 14.656,-21.806 h1.52
M15 Courtyards Top:
  text ".Layer_Name" at 14.656,-21.806 h1.52
M16 Courtyards Bottom:
  text ".Layer_Name" at 14.656,-21.806 h1.52
Drill Drawing:
  lines w0.254: 71.405,4.614 72.809,4.614 72.809,6.017 71.405,6.017 71.405,4.614 ; 71.405,8.123 71.756,8.123 72.107,7.772 72.458,8.123 72.809,8.123 72.458,8.474 72.809,8.824 72.458,8.824 72.107,9.175 71.756,8.824 71.405,8.824 71.756,8.474 71.405,8.123 ; 71.405,12.333 72.809,12.333 72.107,10.93 71.405,12.333
  lines w0.305: 70.133,3.667 152.213,3.667 ; 70.133,13.14 152.213,13.14 ; 78.715,0.509 78.715,16.298 ; 87.147,0.509 87.147,16.298 ; 103.316,0.509 103.316,16.298 ; 109.898,0.509 109.898,16.298 ; 119.427,0.509 119.427,16.298 ; 137.825,0.509 137.825,16.298 ; 70.133,0.509 152.213,0.509 152.213,16.298 70.133,16.298 70.133,0.509
  text "Symbol" at 72.028,14.087 h1.83
  text "Quantity" at 79.662,14.087 h1.83
  text "Finished Hole Size" at 88.095,14.087 h1.83
  text "Plated" at 104.263,14.087 h1.83
  text "Hole Type" at 110.846,14.087 h1.83
  text "Drill Layer Pair" at 120.375,14.087 h1.83
  text "Hole Tolerance" at 138.773,14.087 h1.83
  text "190" at 79.662,10.93 h1.52
  text "11.81mil (0.300mm)" at 88.095,10.93 h1.52
  text "PTH" at 104.263,10.93 h1.52
  text "Round" at 110.846,10.93 h1.52
  text "Top Layer - Bottom Layer" at 120.375,10.93 h1.52
  text "1" at 79.662,7.772 h1.52
  text "40.00mil (1.016mm)" at 88.095,7.772 h1.52
  text "PTH" at 104.263,7.772 h1.52
  text "Round" at 110.846,7.772 h1.52
  text "Top Layer - Bottom Layer" at 120.375,7.772 h1.52
  text "8" at 79.662,4.614 h1.52
  text "43.31mil (1.100mm)" at 88.095,4.614 h1.52
  text "PTH" at 104.263,4.614 h1.52
  text "Round" at 110.846,4.614 h1.52
  text "Top Layer - Bottom Layer" at 120.375,4.614 h1.52
  text "199 Total" at 79.662,1.456 h1.52
  text ".Layer_Name" at 14.656,-21.806 h1.52
M17 Embedded Cavity:
  text ".Layer_Name" at 14.656,-21.806 h1.52
M18 Embedded Assembly:
  text ".Layer_Name" at 14.656,-21.806 h1.52
M19 Embedded Keepout:
  text ".Layer_Name" at 14.91,-21.552 h1.52

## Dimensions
1,19.54 to 0,0 on M2 Board Dimensions
0,0 to 65,1 on M2 Board Dimensions
0,-10.16 to 25.4,-10.16 on M2 Board Dimensions
0,0 to 1,19.54 on M2 Board Dimensions
0,0 to 65,1 on M2 Board Dimensions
